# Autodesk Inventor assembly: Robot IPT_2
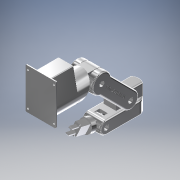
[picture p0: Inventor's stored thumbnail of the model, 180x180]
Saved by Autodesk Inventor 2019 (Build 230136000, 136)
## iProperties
Created: 2018-07
Part Number: Robot IPT_2
Document SubType Name: Assembly
Designer: Power User
Author: Power User
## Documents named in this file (10)
- D:\Karntarat T\06.MFG_Autodesk Inventor file\03.Project Test_byKarn\Practics\Robot IPT\Robot IPT_2.iam
- D:\Karntarat T\06.MFG_Autodesk Inventor file\03.Project Test_byKarn\Practics\Robot IPT\Robot-Base-Model-A.ipt
- D:\Karntarat T\06.MFG_Autodesk Inventor file\03.Project Test_byKarn\Practics\Robot IPT\Robot-Axis1-1.ipt
- D:\Karntarat T\06.MFG_Autodesk Inventor file\03.Project Test_byKarn\Practics\Robot IPT\Robot-Axis1-2.ipt
- D:\Karntarat T\06.MFG_Autodesk Inventor file\03.Project Test_byKarn\Practics\Robot IPT\Robot-Axis1-3.ipt
- D:\Karntarat T\06.MFG_Autodesk Inventor file\03.Project Test_byKarn\Practics\Robot IPT\Robot-Axis1-4.ipt
- D:\Karntarat T\06.MFG_Autodesk Inventor file\03.Project Test_byKarn\Practics\Robot IPT\Robot-Axis1-5.ipt
- D:\Karntarat T\06.MFG_Autodesk Inventor file\03.Project Test_byKarn\Practics\Robot IPT\Robot-Axis1-6.ipt
- D:\Karntarat T\06.MFG_Autodesk Inventor file\03.Project Test_byKarn\Practics\Robot IPT\Robot-Clamp.ipt
- D:\Karntarat T\06.MFG_Autodesk Inventor file\03.Project Test_byKarn\Practics\Robot IPT\Robot-Clamp-Mount.ipt
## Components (10 placed, 9 different names)
1. Robot-Base-Model-A:1 — Insert:1, Angle:2
2. Robot-Axis1-1:1 — Insert:1, Insert:2
3. Robot-Axis1-2:1 — Insert:2, Insert:3, Angle:1, Angle:2, Flush:4
4. Robot-Axis1-3:1 — Insert:3, Insert:4, Flush:1, Angle:1
5. Robot-Axis1-4:1 — Insert:4, Flush:1, Insert:5
6. Robot-Axis1-5:1 — Insert:5, Mate:1, Mate:2
7. Robot-Axis1-6:1 — Mate:1, Mate:2, Insert:6
8. Robot-Clamp:1 — Mate:3, Mate:4, Flush:2
9. Robot-Clamp-Mount:1 — Insert:6, Mate:3, Mate:4, Flush:2, Mate:5, Mate:6, Flush:3
10. Robot-Clamp:2 — Mate:5, Mate:6, Flush:3
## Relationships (18: Insert 6, Mate 6, Flush 4, Angle 2)
- Insert:1: Robot-Base-Model-A:1 ↔ Robot-Axis1-1:1
- Insert:2: Robot-Axis1-1:1 ↔ Robot-Axis1-2:1
- Insert:3: Robot-Axis1-2:1 ↔ Robot-Axis1-3:1
- Insert:4: Robot-Axis1-3:1 ↔ Robot-Axis1-4:1
- Flush:1: Robot-Axis1-3:1 ↔ Robot-Axis1-4:1
- Angle:1: Robot-Axis1-2:1 ↔ Robot-Axis1-3:1
- Angle:2: Robot-Base-Model-A:1 ↔ Robot-Axis1-2:1
- Insert:5: Robot-Axis1-4:1 ↔ Robot-Axis1-5:1
- Mate:1: Robot-Axis1-5:1 ↔ Robot-Axis1-6:1
- Mate:2: Robot-Axis1-5:1 ↔ Robot-Axis1-6:1
- Insert:6: Robot-Axis1-6:1 ↔ Robot-Clamp-Mount:1
- Mate:3: Robot-Clamp:1 ↔ Robot-Clamp-Mount:1
- Mate:4: Robot-Clamp:1 ↔ Robot-Clamp-Mount:1
- Flush:2: Robot-Clamp:1 ↔ Robot-Clamp-Mount:1
- Mate:5: Robot-Clamp-Mount:1 ↔ Robot-Clamp:2
- Mate:6: Robot-Clamp-Mount:1 ↔ Robot-Clamp:2
- Flush:3: Robot-Clamp-Mount:1 ↔ Robot-Clamp:2
- Flush:4: Robot-Axis1-2:1
